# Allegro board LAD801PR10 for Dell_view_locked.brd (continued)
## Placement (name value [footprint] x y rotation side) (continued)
JPWR1  JXT_FP226H-006S1BM  [JXT_FP226H-006S1BM_6P]  159.15 107.31 90 top
JRTC1  ACES_50271-0020N-001  [ACES_50271-0020N-001_2P]  29.83 5.9 180 bottom
JSPK1  JXT_WB247H-004S10M  [JXT_WB247H-004S10M_4P]  11.81 5.67 180 bottom
JSSD1  ACES_50406-03071-001  [ACES_50406-03071-001_30P]  198.85 14.1 180 top
JTP1  JXT_FP202DH-008M10M  [JXT_FP202DH-008M10M_8P]  104.9 9.71 180 bottom
JUSB1  ACON_TARA4-9K1311  [ACON_TARA4-9K1311_9P]  14.68 63.2 90 bottom
JUSB2  ACON_TARA4-9K1311  [ACON_TARA4-9K1311_9P]  14.68 41.5 90 bottom
JWLAN1  LCN_DAN05-67406-0100  [LCN_DAN05-67406-0100_67P]  43.05 100.18 0 bottom
L1  BLM15BD601SN1D_2P  [MURAT_BLM15BD601SN1D_2P]  134.04 43.43 90 top
L2  BLM15BD601SN1D_2P  [MURAT_BLM15BD601SN1D_2P]  91.27 40.98 0 top
L3  MCM1012B900F06BP_4P  [INPAQ_MCM1012B900F06BP_4P]  221.75 35.14 180 bottom
L4  MCM1012B900F06BP_4P  [INPAQ_MCM1012B900F06BP_4P-NPM]  220.88 26.81 270 bottom
L5  BLM15PX221SN1D_2P  [MURAT_BLM15PX221SN1D_2P]  31.13 28.23 270 top
LI1  HCM1012GH900BP_4P  [INPAQ_HCM1012GH900BP_4P-NPM]  16.21 87.01 0 top
LI2  HCM1012GH900BP_4P  [INPAQ_HCM1012GH900BP_4P-NPM]  16.21 89.55 0 top
LI3  HCM1012GH900BP_4P  [INPAQ_HCM1012GH900BP_4P-NPM]  16.21 81.93 0 top
LI4  HCM1012GH900BP_4P  [INPAQ_HCM1012GH900BP_4P-NPM]  16.21 84.47 0 top
LU1  MCM1012B900F06BP_4P  [INPAQ_MCM1012B900F06BP_4P]  25.17 57.68 0 top
LU2  HCM1012GH900BP_4P  [INPAQ_HCM1012GH900BP_4P-NPM]  22.44 62.31 0 top
LU3  HCM1012GH900BP_4P  [INPAQ_HCM1012GH900BP_4P-NPM]  22.44 60.54 0 top
LU4  MCM1012B900F06BP_4P  [INPAQ_MCM1012B900F06BP_4P]  25.68 35.9 0 top
LU5  HCM1012GH900BP_4P  [INPAQ_HCM1012GH900BP_4P-NPM]  22.63 41.23 0 top
LU6  HCM1012GH900BP_4P  [INPAQ_HCM1012GH900BP_4P-NPM]  22.76 38.88 0 top
LU7  MCM1012B900F06BP_4P  [INPAQ_MCM1012B900F06BP_4P]  174.8 20.25 180 bottom
LU8  MCM1012B900F06BP_4P  [INPAQ_MCM1012B900F06BP_4P]  180.82 20.25 180 bottom
LV2  BLM15BD121SN1D_0402  [R_0402]  99.23 115.37 270 top
LV3  BLM15BD121SN1D_0402  [R_0402]  99.41 118.96 270 top
LV4  BLM15BD121SN1D_0402  [R_0402]  97.89 115.1 90 bottom
LV6  BLM15BD221SN1D_2P  [MURAT_BLM15BB221SN1D_2P]  115.58 104.6 90 top
LV7  BLM15BD121SN1D_0402  [R_0402]  120.34 100.07 0 top
LV8  BLM15BD121SN1D_0402  [R_0402]  123.1 100.22 180 top
LW1  MCM1012B900F06BP_4P  [INPAQ_MCM1012B900F06BP_4P-NPM]  42.12 97.46 270 bottom
LX1  MCF12102G900-T_4P  [TAIYO_MCF12102G900-T_4P]  218.36 44.01 270 bottom
LX2  MCF12102G900-T_4P  [TAIYO_MCF12102G900-T_4P]  216.56 43.97 270 bottom
NOREF  -  []  82.28 86.9 0 top
NOREF#2  -  []  77.34 41.48 0 top
NOREF#3  -  []  88.93 117.7 0 top
NOREF#4  -  []  206.6 47.9 0 top
NOREF#5  -  []  52.3 133.7 0 top
NOREF#6  -  []  38.63 56.48 270 top
NOREF#7  -  []  49.63 8.4 0 top
NOREF#8  -  []  -44.7 133.66 0 top
NOREF#9  -  []  166 99.8 0 top
NOREF#10  -  []  27.76 -37.89 0 top
NOREF#11  -  []  100 80.45 0 top
NOREF#12  -  []  18.4 4.3 0 top
NOREF#13  -  []  141.9 6.3 0 top
NOREF#14  -  []  113.5 134.5 0 top
NOREF#15  -  []  5 3.6 0 top
NOREF#16  -  []  82.24 66.05 0 top
NOREF#17  -  []  124.3 17.25 0 top
NOREF#18  -  []  34.53 73.04 270 top
NOREF#19  -  []  121.2 136 0 top
NOREF#20  -  []  141.9 61.2 0 top
NOREF#21  -  []  124.3 80.45 0 top
NOREF#22  -  []  -0.3 173.69 0 top
NOREF#23  -  []  8.7 122.3 0 top
NOREF#24  -  []  136.5 90.5 0 top
NOREF#25  -  []  100 17.25 0 top
NOREF#26  -  []  73.4 94.39 180 bottom
NOREF#27  -  []  81.35 29.7 90 bottom
NOREF#28  -  []  107.37 95.09 180 bottom
PBATT1  -  [ACES_50458-01001-P01_10P-T]  225.91 17.6 180 bottom
PC1  1000P_0402_50V7K  [C_0402]  157.51 123.91 180 top
PC2  0.1U_0402_25V7K  [C_0402]  157.51 122.96 180 top
PC3  1000P_0402_50V7K  [C_0402]  156.75 118.77 180 top
PC4  0.1U_0402_25V7K  [C_0402]  156.75 119.66 180 top
PC7  0.01U_0402_25V7K  [C_0402]  200.55 19.53 270 bottom
PC8  1000P_0402_50V7K  [C_0402]  203.47 15.28 270 bottom
PC14  .1U_0402_16V7K  [C_0402]  179.11 27.47 0 top
PC16  .1U_0402_16V7K  [C_0402]  178.26 21.98 90 top
PC100  1000P_0402_25V8J  [C_0402]  179.34 44.17 270 top
PC102  0.1U_0402_10V7K  [C_0402]  172.27 46.45 270 bottom
PC103  2200P_0402_50V7K  [C_0402]  178.45 44.17 270 bottom
PC104  10U_0805_25V6K  [C_0805]  176.72 45.89 0 top
PC105  10U_0805_25V6K  [C_0805]  176.72 45.89 0 bottom
PC106  22U_0805_6.3V6M  [C_0805]  161.53 40.21 270 bottom
PC107  22U_0805_6.3V6M  [C_0805]  163.3 39.45 270 bottom
PC108  22U_0805_6.3V6M  [C_0805]  160.45 42.82 90 bottom
PC109  22U_0805_6.3V6M  [C_0805]  159.75 40.21 270 bottom
PC110  22U_0805_6.3V6M  [C_0805]  162.24 42.82 90 bottom
PC111  4.7U_0603_6.3V6M  [C_0603]  177.16 41.76 90 top
PC112  680P_0603_50V7K  [C_0603]  166.58 43.08 270 top
PC113  1000P_0402_25V8J  [C_0402]  175.28 39.6 270 bottom
PC114  0.1U_0402_10V7K  [C_0402]  174.9 36.49 270 bottom
PC115  1000P_0402_25V8J  [C_0402]  182.07 34.38 270 top
PC116  2200P_0402_50V7K  [C_0402]  181.18 34.39 270 bottom
PC117  10U_0805_25V6K  [C_0805]  179.75 35.92 0 bottom
PC118  10U_0805_25V6K  [C_0805]  179.75 35.9 0 top
PC119  4.7U_0603_6.3V6M  [C_0603]  176.68 31.46 0 top
PC120  22U_0805_6.3V6M  [C_0805]  174.94 23.2 0 bottom
PC121  22U_0805_6.3V6M  [C_0805]  174.94 24.92 0 bottom
PC122  22U_0805_6.3V6M  [C_0805]  174.94 26.63 0 bottom
PC123  22U_0805_6.3V6M  [C_0805]  170.67 23.71 180 bottom
PC124  22U_0805_6.3V6M  [C_0805]  170.67 25.42 180 bottom
PC125  680P_0603_50V7K  [C_0603]  173.18 30.95 180 top
PC126  4.7U_0603_6.3V6M  [C_0603]  176.23 29.36 270 bottom
PC127  1000P_0402_25V8J  [C_0402]  179.09 29.37 270 bottom
PC128  4.7U_0402_6.3V6M  [C_0402]  181.74 29.36 0 bottom
PC130  0.1U_0402_25V6  [C_0402]  179.34 44.17 270 bottom
PC131  1000P_0402_25V8J  [C_0402]  178.45 44.17 270 top
PC132  0.1U_0402_25V6  [C_0402]  181.19 34.38 270 top
PC133  1000P_0402_25V8J  [C_0402]  182.07 34.39 270 bottom
PC200  0.1U_0402_10V7K  [C_0402]  85.55 108.75 270 bottom
PC201  2200P_0402_50V7K  [C_0402]  81.86 109.14 0 bottom
PC202  0.1U_0402_10V7K  [C_0402]  88.41 101.64 270 bottom
PC203  0.1U_0402_10V7K  [C_0402]  89.3 101.64 270 bottom
PC204  1U_0603_10V6K  [C_0603]  82.57 104.86 0 bottom
PC205  10U_0805_6.3V6K  [C_0805]  93.17 105.47 90 bottom
PC206  10U_0805_25V6K  [C_0805]  81.53 107.85 0 top
PC207  680P_0402_50V7K  [C_0402]  76.74 103.78 180 top
PC208  0.1U_0402_25V6  [C_0402]  81.86 109.14 0 top
PC209  1U_0603_10V6K  [C_0603]  84.47 101.24 270 bottom
PC210  0.033U_0402_16V7K  [C_0402]  91.06 104.42 0 bottom
PC211  10U_0805_6.3V6K  [C_0805]  91.46 105.47 90 bottom
PC212  10U_0805_25V6K  [C_0805]  81.53 107.85 0 bottom
PC213  .1U_0402_16V7K  [C_0402]  91.06 103.53 0 bottom
PC214  220P_0402_25V8J  [C_0402]  91.07 101.71 90 bottom
PC215  22U_0603_6.3V6M  [C_0603]  67.3 105.68 90 top
PC216  22U_0603_6.3V6M  [C_0603]  66.03 105.68 90 top
PC217  22U_0603_6.3V6M  [C_0603]  66.02 105.68 90 bottom
PC218  22U_0603_6.3V6M  [C_0603]  64.76 105.68 90 bottom
PC219  22U_0603_6.3V6M  [C_0603]  64.76 105.68 90 top
PC220  22U_0603_6.3V6M  [C_0603]  67.29 105.68 90 bottom
PC230  1000P_0402_25V8J  [C_0402]  81.86 110.03 0 top
PC231  1000P_0402_25V8J  [C_0402]  81.86 110.03 0 bottom
PC301  2200P_0402_50V7K  [C_0402]  155.21 43.34 270 bottom
PC302  0.1U_0402_25V6  [C_0402]  157.88 43.34 270 bottom
PC303  10U_0805_25V6K  [C_0805]  153.88 44.31 270 bottom
PC304  0.1U_0402_25V6  [C_0402]  154.39 40.4 90 bottom
PC305  1U_0402_6.3V6K  [C_0402]  147.28 39.66 270 bottom
PC306  2.2U_0402_6.3V6M  [C_0402]  146.39 39.66 270 bottom
PC307  0.1U_0402_10V7K  [C_0402]  147.72 46.58 270 bottom
PC308  680P_0603_50V7K  [C_0603]  142.39 46.7 180 bottom
PC309  330P_0402_50V7K  [C_0402]  149.93 38.63 0 bottom
PC310  22U_0603_6.3V6M  [C_0603]  140.48 39.71 270 bottom
PC311  22U_0603_6.3V6M  [C_0603]  139.21 39.71 270 bottom
PC312  22U_0603_6.3V6M  [C_0603]  139.85 45.93 90 bottom
PC313  22U_0603_6.3V6M  [C_0603]  138.58 45.93 90 bottom
PC320  2200P_0402_50V7K  [C_0402]  156.99 43.34 270 bottom
PC321  0.1U_0402_25V6  [C_0402]  156.1 43.34 270 bottom
PC501  22U_0603_6.3V6M  [C_0603]  159.34 37.34 0 bottom
PC502  0.1U_0402_10V7K  [C_0402]  160.79 32.79 0 bottom
PC503  22P_0402_50V8J  [C_0402]  159.92 32.79 180 bottom
PC504  680P_0402_50V7K  [C_0402]  162.21 35.01 180 top
PC505  22U_0603_6.3V6M  [C_0603]  166.02 26.62 0 bottom
PC506  22U_0603_6.3V6M  [C_0603]  166.02 27.87 0 bottom
PC507  22U_0603_6.3V6M  [C_0603]  166.02 27.87 0 top
PC601  680P_0402_50V7K  [C_0402]  157.96 55.84 180 top
PC602  0.1U_0402_25V6  [C_0402]  167.2 48.85 0 bottom
PC603  1U_0603_10V6K  [C_0603]  163.66 50.88 90 bottom
PC604  0.22U_0603_25V7K  [C_0603]  162.64 46.82 180 top
PC605  47P_0402_50V8J~D  [C_0402]  169.56 48.8 270 top
PC606  33U_25V_M  [C_25CL33LD]  161.75 66.91 270 bottom
PC608  10U_0805_25V6K  [C_0805]  149.22 58.7 0 bottom
PC611  0.22U_0402_16V7K  [C_0402]  153.19 54.12 0 bottom
PC612  10U_0805_25V6K  [C_0805]  149.22 60.48 0 bottom
PC613  330P_0402_50V8J  [C_0402]  166.69 51.38 0 bottom
PC614  2200P_0402_50V7K  [C_0402]  165.42 53.93 0 bottom
PC616  33P_0402_50V8J  [C_0402]  166.25 52.27 0 bottom
PC617  220P_0402_50V7K  [C_0402]  169.8 54.13 0 top
PC618  330P_0402_50V7K  [C_0402]  170.72 53.24 180 bottom
PC619  0.01U_0402_50V7K  [C_0402]  170.72 52.35 180 bottom
PC620  0.082U_0402_16V7K  [C_0402]  168.93 53.25 270 bottom
PC621  680P_0402_50V7K  [C_0402]  169.8 51.44 0 top
PC622  680P_0603_50V7K  [C_0603]  146.77 55.46 0 top
PC624  0.068U_0402_16V7K  [C_0402]  168.93 54.43 90 bottom
PC625  330P_0402_50V7K  [C_0402]  165.24 55.27 90 bottom
PC626  0.033U_0402_16V7K  [C_0402]  169.82 54.43 90 bottom
PC627  2200P_0402_50V7K  [C_0402]  169.83 55.33 180 top
PC628  10P_0402_50V8J  [C_0402]  161.42 52.91 0 bottom
PC629  2200P_0402_50V7K  [C_0402]  161.68 55.78 0 bottom
PC630  2200P_0402_50V7K  [C_0402]  159.72 56.72 90 top
PC631  1200P_0402_50V7K  [C_0402]  162.32 51.13 90 bottom
PC632  2200P_0402_25V7K  [C_0402]  159.67 50.13 180 top
PC633  6800P_0402_25V7K  [C_0402]  159.66 52.81 270 top
PC636  33P_0402_50V8J  [C_0402]  164.35 55.27 90 bottom
PC637  0.033U_0402_16V7K  [C_0402]  157.88 52.81 270 top
PC639  2200P_0402_25V7K  [C_0402]  163.34 58.3 90 top
PC640  2200P_0402_25V7K  [C_0402]  157.94 54.96 270 top
PC641  .1U_0402_16V7K  [C_0402]  171.09 56.21 90 bottom
PC642  0.047U_0402_25V7K  [C_0402]  159.23 56.73 180 bottom
PC643  330P_0402_50V7K  [C_0402]  161.42 53.81 0 bottom
PC644  .1U_0402_16V7K  [C_0402]  156.99 50.11 90 top
PC645  .1U_0402_16V7K  [C_0402]  157.44 57.63 270 bottom
PC646  0.047U_0402_25V7K  [C_0402]  159.23 57.62 180 bottom
PC647  680P_0402_50V7K  [C_0402]  167.28 59.26 90 top
PC649  0.01U_0402_50V7K  [C_0402]  159.73 54.95 180 bottom
PC650  0.082U_0402_16V7K  [C_0402]  158.82 54.06 0 bottom
PC651  330P_0402_50V7K  [C_0402]  162.45 59.22 270 top
PC652  330P_0402_50V7K  [C_0402]  157.94 54.05 90 bottom
PC653  0.082U_0402_16V7K  [C_0402]  162.46 57.43 180 top
PC654  0.01U_0402_50V7K  [C_0402]  161.05 59.22 270 top
PC655  0.22U_0402_16V7K  [C_0402]  163.16 69.81 180 bottom
PC656  10U_0805_25V6K  [C_0805]  157.63 68.1 180 top
PC657  10U_0805_25V6K  [C_0805]  157.63 66.32 180 bottom
PC658  10U_0805_25V6K  [C_0805]  157.64 68.05 180 bottom
PC659  0.1U_0402_25V6K~D  [C_0402]  157.75 64.92 180 top
PC660  2200P_0402_50V7K  [C_0402]  157.75 63.97 180 bottom
PC661  1U_0402_10V6K  [C_0402]  162.31 72.54 0 bottom
PC662  680P_0603_50V7K  [C_0603]  153.12 69.43 0 top
PC666  0.1U_0402_25V6K~D  [C_0402]  158.95 74.77 180 top
PC667  2200P_0402_50V7K  [C_0402]  158.77 74.62 180 bottom
PC671  0.22U_0402_16V7K  [C_0402]  163.18 79.59 180 bottom
PC672  10U_0805_25V6K  [C_0805]  159.06 75.94 180 bottom
PC673  10U_0805_25V6K  [C_0805]  159.06 77.67 180 bottom
PC677  1U_0402_10V6K  [C_0402]  162.25 82.13 0 bottom
PC678  680P_0603_50V7K  [C_0603]  153.37 78.19 270 top
PC679  1000P_0402_50V7K  [C_0402]  158.97 78.32 180 top
PC680  1000P_0402_50V7K  [C_0402]  157.7 65.87 180 top
PC685  1U_0402_10V6K  [C_0402]  151.15 51.7 90 top
PC686  10P_0402_25V8J  [C_0402]  157.75 64.92 180 bottom
PC688  10P_0402_25V8J  [C_0402]  158.97 76.54 180 top
PC690  33U_25V_M  [C_25CL33LD]  169.21 67.02 270 bottom
PC691  1000P_0402_25V8J  [C_0402]  157.75 63.97 180 top
PC692  1000P_0402_25V8J  [C_0402]  158.97 77.43 180 top
PC693  1000P_0402_25V8J  [C_0402]  158.97 75.66 180 top
PC694  1000P_0402_25V8J  [C_0402]  157.69 66.76 180 top
PC695  10P_0402_25V8J  [C_0402]  168.3 47.77 180 bottom
PC705  2200P_0402_25V7K  [C_0402]  198.96 30.11 90 bottom
PC708  0.1U_0402_25V6  [C_0402]  194.38 40.16 0 bottom
PC711  0.01UF_0402_25V7K  [C_0402]  189.81 32.23 0 top
PC721  0.22U_0402_16V7K  [C_0402]  199.74 35.33 180 bottom
PC742  5600P_0402_25V7K  [C_0402]  156.62 108.23 180 bottom
PC744  0.1U_0402_25V6  [C_0402]  158.57 109.24 0 bottom
PC747  0.1U_0402_25V6  [C_0402]  193.58 32.15 180 bottom
PC748  0.1U_0402_25V7K  [C_0402]  188.94 37.93 180 bottom
PC749  2200P_0402_25V7K  [C_0402]  188.03 39.33 0 bottom
PC750  0.22U_0603_25V7K  [C_0603]  194.71 30.69 90 bottom
PC751  560P_0402_50V7K  [C_0402]  190.39 42.01 270 bottom
PC752  0.015U_0402_25V7K  [C_0402]  190.38 42.89 0 bottom
PC753  10P_0402_50V8J  [C_0402]  192.6 41.93 0 bottom
PC757  1U_0603_25V6  [C_0603]  199.42 38.93 180 bottom
PC760  10U_0805_25V6K  [C_0805]  200.25 30.02 90 bottom
PC761  10U_0805_25V6K  [C_0805]  215.58 23.84 0 bottom
PC762  10U_0805_25V6K  [C_0805]  200.25 30.02 90 top
PC763  10U_0805_25V6K  [C_0805]  201.96 30.02 90 top
PC764  10U_0805_25V6K  [C_0805]  201.96 30.02 90 bottom
PC765  0.1U_0402_25V7K  [C_0402]  198.08 30.11 90 bottom
PC766  10U_0805_25V6K  [C_0805]  215.59 22.12 0 bottom
PC767  680P_0603_50V7K  [C_0603]  210.46 33.81 270 top
PC768  1U_0402_16V6K  [C_0402]  200.18 37.68 180 bottom
PC769  1U_0402_16V6K  [C_0402]  200.18 36.79 180 bottom
PC775  10U_0805_25V6K  [C_0805]  214.14 21.77 270 bottom
PC776  10U_0805_25V6K  [C_0805]  215.58 22.12 0 top
PC777  0.1U_0402_25V7K  [C_0402]  215.72 25.17 0 bottom
PC778  10U_0805_25V6K  [C_0805]  215.58 23.83 0 top
PC779  0.1U_0402_25V7K  [C_0402]  210.01 25.69 270 top
PC780  1000P_0402_25V8J  [C_0402]  198.96 30.11 90 top
PC781  1000P_0402_25V8J  [C_0402]  198.08 30.11 90 top
PC790  0.01U_0402_16V7K  [C_0402]  187.9 37.93 0 top
PC801  1U_0402_6.3V6K  [C_0402]  52.11 3.15 0 bottom
PC802  10U_0805_10V6K  [C_0805]  54.42 5.29 270 bottom
PC803  0.01U_0402_25V7K  [C_0402]  44.32 6.69 90 bottom
PC804  10U_0805_10V6K  [C_0805]  44.9 5.48 270 bottom
PC805  0.1U_0402_10V6K  [C_0402]  53.99 8.57 0 bottom
PC836  330U_2V_M  [C_5X4P5]  86.91 124.92 180 bottom
PC837  330U_2V_M  [C_5X4P5]  86.97 131.08 180 bottom
PC838  330U_2V_M  [C_5X4P5]  81.02 120.86 0 bottom
PC839  330U_2V_M  [C_5X4P5]  89.01 110.57 180 bottom
PC1001  22U_0603_6.3V6M  [C_0603]  116.57 46.72 90 top
PC1002  22U_0603_6.3V6M  [C_0603]  134.26 60.65 180 bottom
PC1003  22U_0603_6.3V6M  [C_0603]  134.26 64.72 180 bottom
PC1004  22U_0603_6.3V6M  [C_0603]  133.18 67.64 180 bottom
PC1005  22U_0603_6.3V6M  [C_0603]  115.36 46.72 90 top
PC1006  22U_0603_6.3V6M  [C_0603]  133.18 69.04 180 bottom
PC1007  22U_0603_6.3V6M  [C_0603]  111.74 46.7 90 top
PC1008  22U_0603_6.3V6M  [C_0603]  114.15 46.72 90 top
PC1009  22U_0603_6.3V6M  [C_0603]  112.95 46.7 90 top
PC1010  22U_0603_6.3V6M  [C_0603]  116.57 50.5 270 top
PC1011  22U_0603_6.3V6M  [C_0603]  115.36 50.49 270 top
PC1012  22U_0603_6.3V6M  [C_0603]  133.18 70.43 180 bottom
PC1013  22U_0603_6.3V6M  [C_0603]  133.18 71.83 180 bottom
PC1014  22U_0603_6.3V6M  [C_0603]  132.8 80.09 180 bottom
PC1015  22U_0603_6.3V6M  [C_0603]  132.8 78.69 180 bottom
PC1016  22U_0603_6.3V6M  [C_0603]  112.67 76.92 0 bottom
PC1017  22U_0603_6.3V6M  [C_0603]  116.48 80.73 180 bottom
PC1018  22U_0603_6.3V6M  [C_0603]  112.67 75.65 0 bottom
PC1019  22U_0603_6.3V6M  [C_0603]  112.67 79.46 0 bottom
PC1020  22U_0603_6.3V6M  [C_0603]  112.67 80.73 0 bottom
PC1021  22U_0603_6.3V6M  [C_0603]  116.48 79.46 180 bottom
PC1022  22U_0603_6.3V6M  [C_0603]  112.67 78.19 0 bottom
PC1023  22U_0603_6.3V6M  [C_0603]  111.01 58.88 270 top
PC1024  22U_0603_6.3V6M  [C_0603]  114.62 58.88 270 top
PC1025  22U_0603_6.3V6M  [C_0603]  132.8 82.88 180 bottom
PC1026  22U_0603_6.3V6M  [C_0603]  109.8 58.88 270 top
PC1027  22U_0603_6.3V6M  [C_0603]  132.8 77.36 180 bottom
PC1028  22U_0603_6.3V6M  [C_0603]  114.64 61.3 270 top
PC1029  22U_0603_6.3V6M  [C_0603]  115.84 61.3 270 top
PC1030  1U_0201_6.3V6M  [C_0201]  108.1 48.63 270 top
PC1031  1U_0201_6.3V6M  [C_0201]  110.22 53.87 270 top
PC1032  1U_0201_6.3V6M  [C_0201]  110.81 48.18 90 top
PC1033  1U_0201_6.3V6M  [C_0201]  109.05 53.87 270 top
PC1034  1U_0201_6.3V6M  [C_0201]  109.67 50.41 270 top
PC1035  1U_0201_6.3V6M  [C_0201]  110.8 53.87 270 top
PC1036  1U_0201_6.3V6M  [C_0201]  109.68 48.18 90 top
PC1037  1U_0201_6.3V6M  [C_0201]  110.25 48.18 90 top
PC1038  1U_0201_6.3V6M  [C_0201]  108.1 49.38 90 top
PC1039  1U_0201_6.3V6M  [C_0201]  110.23 50.41 270 top
PC1040  1U_0201_6.3V6M  [C_0201]  111.15 61.46 270 top
PC1041  1U_0201_6.3V6M  [C_0201]  110 61.46 270 top
PC1042  1U_0201_6.3V6M  [C_0201]  108.31 58.18 0 top
PC1043  1U_0201_6.3V6M  [C_0201]  110.74 56.15 270 top
PC1044  1U_0201_6.3V6M  [C_0201]  111.32 56.15 270 top
PC1045  1U_0201_6.3V6M  [C_0201]  109.58 56.15 270 top
PC1046  1U_0201_6.3V6M  [C_0201]  110.03 60.28 0 top
PC1047  1U_0201_6.3V6M  [C_0201]  110.17 56.15 270 top
PC1048  1U_0201_6.3V6M  [C_0201]  117.34 54.37 180 top
PC1049  1U_0201_6.3V6M  [C_0201]  109.01 56.14 270 top
PC1050  1U_0201_6.3V6M  [C_0201]  110.8 50.4 270 top
PC1051  1U_0201_6.3V6M  [C_0201]  111.51 54.34 0 top
PC1052  1U_0201_6.3V6M  [C_0201]  111.51 53.74 0 top
PC1053  1U_0201_6.3V6M  [C_0201]  110.78 51.62 90 top
PC1054  1U_0201_6.3V6M  [C_0201]  110.22 51.62 90 top
PC1055  1U_0201_6.3V6M  [C_0201]  117.34 53.8 180 top
PC1056  1U_0201_6.3V6M  [C_0201]  110.03 59.71 0 top
PC1057  22U_0603_6.3V6M  [C_0603]  117.24 43.2 90 top
PC1058  22U_0603_6.3V6M  [C_0603]  137.44 51.7 180 top
PC1059  22U_0603_6.3V6M  [C_0603]  137.44 53.1 180 top
PC1060  22U_0603_6.3V6M  [C_0603]  137.44 54.75 180 top
PC1061  22U_0603_6.3V6M  [C_0603]  116.54 51.54 90 top
PC1062  220U 2V Y D2  [C_D2]  137.18 69.02 90 bottom
PC1063  330U_2V_M  [C_5X4P5]  136.33 79.86 270 bottom
PC1064  22U_0603_6.3V6M  [C_0603]  115.34 51.53 90 top
PC1065  22U_0603_6.3V6M  [C_0603]  114.13 51.53 90 top
PC1066  22U_0603_6.3V6M  [C_0603]  112.92 51.53 90 top
PC1067  22U_0603_6.3V6M  [C_0603]  111.72 51.53 90 top
PC1068  22U_0603_6.3V6M  [C_0603]  133.18 66.24 180 bottom
PC1069  22U_0603_6.3V6M  [C_0603]  136.61 64.72 180 bottom
PC1070  22U_0603_6.3V6M  [C_0603]  135.53 66.5 180 top
PC1071  22U_0603_6.3V6M  [C_0603]  135.53 69.29 180 top
PC1072  22U_0603_6.3V6M  [C_0603]  134.26 62.05 180 bottom
PC1073  22U_0603_6.3V6M  [C_0603]  135.53 67.89 180 top
PC1074  22U_0603_6.3V6M  [C_0603]  138.01 67.13 180 top
PC1075  22U_0603_6.3V6M  [C_0603]  138.01 65.73 180 top
PC1076  22U_0603_6.3V6M  [C_0603]  134.26 64.72 180 top
PC1077  22U_0603_6.3V6M  [C_0603]  134.26 63.32 180 top
PC1078  22U_0603_6.3V6M  [C_0603]  133.18 71.83 180 top
PC1079  22U_0603_6.3V6M  [C_0603]  133.18 70.43 180 top
PC1080  22U_0603_6.3V6M  [C_0603]  133.18 69.04 180 top
PC1081  22U_0603_6.3V6M  [C_0603]  133.18 67.64 180 top
PC1082  22U_0603_6.3V6M  [C_0603]  133.18 66.24 180 top
PC1083  1U_0201_6.3V6M  [C_0201]  109.62 51.61 90 top
PC1084  1U_0201_6.3V6M  [C_0201]  109.05 51.61 90 top
PC1085  1U_0201_6.3V6M  [C_0201]  118.96 49.5 270 top
PC1086  1U_0201_6.3V6M  [C_0201]  110.24 47.11 270 top
PC1087  1U_0201_6.3V6M  [C_0201]  110.81 47.11 270 top
PC1088  1U_0201_6.3V6M  [C_0201]  109.63 53.87 270 top
PC1089  1U_0201_6.3V6M  [C_0201]  117.27 45.92 180 top
PC1090  1U_0201_6.3V6M  [C_0201]  117.27 45.36 180 top
PC1091  1U_0201_6.3V6M  [C_0201]  112.17 45.36 0 top
PC1092  1U_0201_6.3V6M  [C_0201]  114.42 45.93 180 top
PC1093  1U_0201_6.3V6M  [C_0201]  115.03 45.36 0 top
PC1094  1U_0201_6.3V6M  [C_0201]  115.03 45.93 0 top
PC1095  1U_0201_6.3V6M  [C_0201]  114.42 45.36 180 top
PC1096  1U_0201_6.3V6M  [C_0201]  112.17 45.93 0 top
PC1097  1U_0201_6.3V6M  [C_0201]  111.55 45.93 180 top
PC1098  1U_0201_6.3V6M  [C_0201]  111.56 45.36 180 top
PC1099  1U_0201_6.3V6M  [C_0201]  109.33 45.93 0 top
PC1103  10U_0805_25V6K  [C_0805]  66.17 127.67 270 bottom
PC1104  10U_0805_25V6K  [C_0805]  66.17 114.32 90 top
PC1105  10U_0805_25V6K  [C_0805]  66.17 114.32 90 bottom
PC1106  2200P_0402_50V7K  [C_0402]  64 126.95 270 bottom
PC1107  0.1U_0402_25V6K  [C_0402]  63.96 114.54 90 bottom
PC1108  0.22U_0402_16V7K  [C_0402]  59.72 124.48 180 top
PC1109  680P_0603_50V7K  [C_0603]  67.79 129.06 270 top
PC1110  1U_0603_10V6K  [C_0603]  58.44 128.93 270 top
PC1111  1U_0603_10V6K  [C_0603]  56.03 127.53 90 top
PC1112  10U_0805_25V6K  [C_0805]  66.17 127.67 270 top
PC1113  10U_0805_25V6K  [C_0805]  62.69 127.11 270 top
PC1114  10U_0805_25V6K  [C_0805]  62.31 114.3 90 top
PC1115  2200P_0402_50V7K  [C_0402]  64.85 114.54 90 bottom
PC1116  0.1U_0402_25V6  [C_0402]  64.89 126.95 270 bottom
PC1117  1000P_0402_50V7K  [C_0402]  48.2 120.48 0 top
PC1118  0.22U_0402_16V7K  [C_0402]  59.34 121.69 180 top
PC1119  0.22U_0402_10V6K  [C_0402]  50.18 117.8 90 top
PC1120  0.22U_0402_10V6K  [C_0402]  51.07 117.8 90 top
PC1121  680P_0603_50V7K  [C_0603]  69.7 114.64 180 top
PC1122  1000P_0402_50V7K  [C_0402]  53.92 116.42 0 top
PC1123  180P_0402_50V8J  [C_0402]  57.6 118.71 0 top
PC1124  330P_0402_50V7K  [C_0402]  53.92 118.71 0 top
PC1125  1U_0201_6.3V6M  [C_0201]  109.33 45.36 0 top
PC1126  1U_0201_6.3V6M  [C_0201]  109.67 47.11 270 top
PC1127  220U 2V Y D2  [C_D2]  142.7 69.02 90 bottom
PC1128  330U_2V_M  [C_5X4P5]  142.45 79.86 270 bottom
PC1129  22U_0603_6.3V6M  [C_0603]  117.05 58.88 270 top
PC1130  22U_0603_6.3V6M  [C_0603]  116.48 76.92 180 bottom
PC1131  22U_0603_6.3V6M  [C_0603]  112.22 61.3 270 top
PC1132  22U_0603_6.3V6M  [C_0603]  116.48 75.65 180 bottom
PC1133  22U_0603_6.3V6M  [C_0603]  115.84 58.88 270 top
PC1134  22U_0603_6.3V6M  [C_0603]  113.43 58.88 270 top
PC1135  22U_0603_6.3V6M  [C_0603]  112.21 58.88 270 top
PC1136  22U_0603_6.3V6M  [C_0603]  116.48 78.19 180 bottom
PC1137  22U_0603_6.3V6M  [C_0603]  117.05 61.3 270 top
PC1138  22U_0603_6.3V6M  [C_0603]  113.43 61.3 270 top
PC1139  22U_0603_6.3V6M  [C_0603]  137.44 54.75 180 bottom
PC1140  22U_0603_6.3V6M  [C_0603]  137.43 51.71 180 bottom
PC1141  22U_0603_6.3V6M  [C_0603]  137.44 53.1 180 bottom
PC1142  22U_0603_6.3V6M  [C_0603]  114.83 43.2 90 top
PC1143  22U_0603_6.3V6M  [C_0603]  113.62 43.2 90 top
PC1144  22U_0603_6.3V6M  [C_0603]  112.42 43.2 90 top
PC1145  22U_0603_6.3V6M  [C_0603]  111.21 43.2 90 top
PC1146  22U_0603_6.3V6M  [C_0603]  116.03 43.2 90 top
PC1147  1U_0201_6.3V6M  [C_0201]  109.75 43.87 90 top
PC1148  1U_0201_6.3V6M  [C_0201]  109.19 43.87 90 top
PC1149  1U_0201_6.3V6M  [C_0201]  110.79 42.44 0 top
PC1150  1U_0201_6.3V6M  [C_0201]  110 42.73 270 top
PC1151  1U_0201_6.3V6M  [C_0201]  109.43 43.24 270 top
PC1152  1U_0201_6.3V6M  [C_0201]  113.82 42.36 180 top
PC1153  1U_0201_6.3V6M  [C_0201]  110.31 43.87 90 top
PC1164  1U_0201_6.3V6M  [C_0201]  107.5 50.51 180 top
PC1170  22U_0603_6.3V6M  [C_0603]  114.15 50.49 270 top
PC1171  22U_0603_6.3V6M  [C_0603]  111.74 50.49 270 top
PC1172  22U_0603_6.3V6M  [C_0603]  112.95 50.49 270 top
PC1173  22U_0603_6.3V6M  [C_0603]  136.61 63.32 180 bottom
PC1174  22U_0603_6.3V6M  [C_0603]  134.26 63.32 180 bottom
PC1175  22U_0603_6.3V6M  [C_0603]  113.43 56.53 270 top
PC1176  22U_0603_6.3V6M  [C_0603]  117.05 56.53 270 top
PC1177  22U_0603_6.3V6M  [C_0603]  115.84 56.53 270 top
PC1178  22U_0603_6.3V6M  [C_0603]  113.43 74.38 0 bottom
PC1179  22U_0603_6.3V6M  [C_0603]  132.8 84.28 180 bottom
PC1180  22U_0603_6.3V6M  [C_0603]  112.64 75.65 0 top
PC1181  22U_0603_6.3V6M  [C_0603]  114.64 56.53 270 top
PC1182  22U_0603_6.3V6M  [C_0603]  116.48 75.65 180 top
PC1183  22U_0603_6.3V6M  [C_0603]  112.22 56.53 270 top
PC1184  22U_0603_6.3V6M  [C_0603]  132.8 81.48 180 bottom
PC1190  2200P_0402_50V7K  [C_0402]  64.89 126.95 270 top
PC1191  0.1U_0402_25V6K  [C_0402]  64 126.95 270 top
PC1192  2200P_0402_50V7K  [C_0402]  64.85 114.54 90 top
PC1193  0.1U_0402_25V6  [C_0402]  63.96 114.54 90 top
PC1226  0.1U_0402_25V6K  [C_0402]  49.12 124.93 180 top
PC1227  820P_0402_50V7K  [C_0402]  53.04 117.8 90 top
PC1228  390P_0402_50V7K  [C_0402]  58.5 116.91 90 top
PC1229  0.01U_0402_50V7K  [C_0402]  56.61 118.71 180 top
PC1230  0.15U_0603_16V7K  [C_0603]  50.25 116.74 0 top
PC1231  0.1U_0603_50V7K  [C_0603]  53.99 114.2 0 top
PC1232  0.033U_0402_16V7K  [C_0402]  50.11 115.66 0 top
PC1233  330P_0402_50V  [C_0402]  57.5 115.02 180 top
PC1401  2200P_0402_50V7K  [C_0402]  159.07 96.42 0 bottom
PC1402  0.1U_0402_25V6  [C_0402]  159.07 97.31 0 bottom
PC1403  10U_0805_25V6K  [C_0805]  158.36 93.3 0 bottom
PC1404  0.1U_0402_25V6  [C_0402]  160.29 87.51 90 bottom
PC1405  1U_0402_6.3V6K  [C_0402]  152.48 86.65 270 bottom
PC1406  2.2U_0402_6.3V6M  [C_0402]  151.59 86.65 270 bottom
PC1407  0.1U_0402_10V7K  [C_0402]  153.05 94.27 270 bottom
PC1408  680P_0603_50V7K  [C_0603]  147.97 93.75 180 bottom
PC1409  330P_0402_50V7K  [C_0402]  155.14 85.75 0 bottom
PC1411  22U_0603_6.3V6M  [C_0603]  142.7 88.03 180 bottom
PC1412  22U_0603_6.3V6M  [C_0603]  142.7 89.24 180 bottom
PC1413  22U_0603_6.3V6M  [C_0603]  142.7 90.45 180 bottom
PC1414  22U_0603_6.3V6M  [C_0603]  142.7 91.65 180 bottom
PC1420  1000P_0402_25V8J  [C_0402]  158.25 94.64 0 bottom
PC1421  1000P_0402_25V8J  [C_0402]  158.25 95.53 0 bottom
PD2  -  [TVNST52302AB0_SOT523-3]  215.21 12.34 180 top
PD3  -  [TVNST52302AB0_SOT523-3]  217.37 12.35 180 top
PD4  -  [TVNST52302AB0_SOT523-3]  157.66 121.75 270 bottom
PD5  -  [BAV99W_SC70-3]  165.88 128.84 180 bottom
PD6  -  [BAV99W_SC70-3]  162.23 126.52 270 bottom
PD102  -  [SDMK0340L-7-F_SOD323-2]  179.6 29.04 0 top
PD704  -  [LRB715FT1G_SOT323-3]  202.14 39.65 0 bottom
PH601  470K_0402_5%_ TSM0B474J4702RE  [R_0402]  157.97 84.02 180 bottom
PH602  10K_0402_5%_ERTJ0ER103J  [R_0402]  154.59 83.97 0 bottom
PH603  470K_0402_5%_ TSM0B474J4702RE  [R_0402]  155.25 74.31 0 bottom
PH604  10KB_0402_5%_ERTJ0ER103J  [R_0402]  142.64 49.3 180 bottom
PH605  10KB_0402_5%_ERTJ0ER103J  [R_0402]  150.72 66.95 180 bottom
PH1101  470K_0402_5%_TSM0B474J4702RE  [R_0402]  46.39 119.64 270 top
PH1102  10K_0402_5%_ERTJ0ER103J  [R_0402]  75.69 110.05 180 bottom
PJP1  JUMP_43X79  [JUMP_43X79-NPM]  159.2 119.84 90 top
PJP2  JUMP_43X79  [JUMP_43X79-NPM]  166.49 120.9 0 top
PJP3  JUMP_43X79  [JUMP_43X79-NPM]  202.94 18.88 90 bottom
PJP102  -  [JUMP_43X118]  160.78 41.11 180 top
PJP103  -  [JUMP_43X118]  173.01 24.01 270 top
PJP105  -  [JUMP_43X79]  175.85 49.34 270 bottom
PJP106  -  [JUMP_43X79]  180.45 39.39 270 bottom
PJP200  -  [JUMP_43X118]  66 102.83 270 top
PJP203  -  [JUMP_43X79]  94.32 102.66 90 bottom
PJP206  -  [JUMP_43X79]  71.3 108.9 180 top
PJP301  -  [JUMP_43X79]  157.34 45.72 180 bottom
PJP302  -  [JUMP_43X118]  138.74 42.82 180 bottom
PJP501  -  [JUMP_43X79]  156.93 38.86 270 bottom
PJP502  -  [JUMP_43X79]  162.97 27.49 270 bottom
PJP601  PAD-OPEN 4X4M  [JUMP_43X118]  166.12 75.08 0 bottom
PJP603  PAD-OPEN1X1M  [JUMP_43X39]  149.42 62.51 0 bottom
PJP701  -  [JUMP_43X118]  200.64 24.9 90 bottom
PJP801  -  [JUMP_43X79]  57.81 5.22 180 bottom
PJP802  -  [JUMP_43X79]  41.81 6.78 90 bottom
PJP1101  -  [JUMP_43X79]  65.41 131.02 270 bottom
PJP1401  -  [JUMP_43X79]  157.92 100.35 270 bottom
PJP1402  -  [JUMP_43X118]  143.47 93.64 90 bottom
PJPDC1  ACES_50458-00601-001  [ACES_50458-00601-001_6P-T]  169.13 124.38 180 top
PL1  HCB3225KF-151T50_2P  [5A_Z150_1210_2P]  159.19 121.71 270 top
PL2  BLM15AG102SN1D_2P  [MURAT_BLM15AG102SN1D_2P]  162.24 122.38 0 top
PL3  HCB3225KF-151T50_2P  [5A_Z150_1210_2P]  202.91 20.78 270 bottom
PL4  HCB3225KF-151T50_2P  [5A_Z150_1210_2P]  168.38 120.93 180 top
PL100  1.5UH_9A_20%_7X7X3_M  [L_7X7X3_M_2P]  171.09 42.63 180 bottom
PL101  2.2UH_7.8A_20%_7X7X3_M  [L_7X7X3_M_2P]  171.85 34.29 270 bottom
PL102  HCB3225KF-151T50_2P  [5A_Z150_1210_2P-NPM]  175.81 50.14 270 bottom
PL103  HCB3225KF-151T50_2P  [5A_Z150_1210_2P-NPM]  180.48 40.2 270 bottom
PL200  1UH_11A_20%_7X7X3_M  [L_7X7X3_M_2P]  69.89 105.11 0 bottom
PL201  HCB3225KF-151T50_2P  [5A_Z150_1210_2P-NPM]  69.45 108.92 0 top
PL301  1UH_6.6A_20%_5X5X3_M  [L_5X5X3_M_2P]  146.25 42.99 180 bottom
PL302  HCB3225KF-151T50_2P  [5A_Z150_1210_2P-NPM]  158.17 45.7 180 bottom
PL501  1UH_6.6A_20%_5X5X3_M  [L_5X5X3_M_2P]  165.12 34.77 270 bottom
PL601  0.68UH +-20% 7.9A  [L_5X5X3_M]  139.72 52.73 0 bottom
PL602  HCB3225KF-151T50_2P  [5A_Z150_1210_2P-NPM]  165.35 75.04 0 bottom
PL603  .15UH +-20% 29A 7X7X4 MOLDING  [L_7X7X4_M]  147.36 71.21 0 bottom
PL605  .15UH +-20% 29A 7X7X4 MOLDING  [L_7X7X4_M]  147.4 80.61 0 bottom
PL700  4.7UH_5.5A_20%_7X7X3_M  [L_7X7X3_M_2P]  209.12 32.15 0 bottom
PL704  1UH_PCMB053T-1R0MS_7A_20%  [L_5X5X3_M_2P-NPM]  200.67 23.28 90 bottom
PL1101  HCB3225KF-151T50_2P  [5A_Z150_1210_2P-NPM]  65.44 129.12 90 bottom
PL1102  0.22UH_24A_20%_7X7X4_MOLDING  [L_7X7X4_M]  82.36 127.46 180 bottom
PL1103  0.22UH_24A_20%_7X7X4_MOLDING  [L_7X7X4_M]  82.31 114.26 180 bottom
PL1401  1UH_6.6A_20%_5X5X3_M  [L_5X5X3_M_2P]  151.71 90.18 180 bottom
PL1402  HCB3225KF-151T50_2P  [5A_Z150_1210_2P-NPM]  157.94 101.17 270 bottom
PQ1  L2N7002DW1T1G_SC88-6  [2N7002DW-T-R7_SOT363-6]  185.11 21.32 0 top
PQ2  L2N7002DW1T1G_SC88-6  [2N7002DW-T-R7_SOT363-6]  179.62 23.57 270 top
PQ3  -  [L2N7002WT1G_SC70-3]  183.18 25.6 90 top
PQ5  MMST3904-7-F_SOT323  [RHU002N06_SOT323-3]  160.99 127.11 180 bottom
PQ6  FDV301N_G 1N SOT23-3  [FDV301N_NL_SOT23-3]  162.58 121.79 180 bottom
PQ201  -  [AON7934_DFN3X3A8-10]  78.93 106.31 0 bottom
PQ601  AON7934_DFN3X3A-8-10  [AON7934_DFN3X3A8-10]  145.86 56.83 45 bottom
PQ704  AON7408L_DFN8-5  [SIS412DN-T1-GE3_POWERPAK8-5]  206.45 31.28 270 bottom
PQ708  AON7506_DFN33-8-5  [SIS412DN-T1-GE3_POWERPAK8-5]  203.56 33.26 90 bottom
PQ709  -  [L2N7002WT1G_SC70-3]  158.1 106.55 90 bottom
PQ710  -  [LMUN5113T1G_SOT323-3]  201.19 23.58 180 top
PQ711  -  [LTC015EUBFS8TL_UMT3F]  199.32 21.68 270 top
PQ712  -  [L2N7002WT1G_SC70-3]  157.78 104.03 270 bottom
PQ717  -  [MDU1512RH_POWERDFN56-8-5]  209.97 27.2 270 bottom
PQ718  -  [MDU1512RH_POWERDFN56-8-5]  162.24 118.72 0 bottom
PQ720  -  [RUM002N02GT2L_VMT3]  187.53 39.9 90 top
PQ721  -  [RUM002N02GT2L_VMT3]  188.04 35.51 180 top
PQ740  -  [MDU1512RH_POWERDFN56-8-5]  160.26 117 270 bottom
PQ1101  AON6552_DFN5X6-8-5  [SIR472DP-T1-GE3_POWERPAK8-5]  73.53 131.79 270 bottom
PQ1102  AON6554_DFN5X6-8-5  [SIR472DP-T1-GE3_POWERPAK8-5]  68.11 122.33 90 bottom
PQ1103  AON6554_DFN5X6-8-5  [SIR472DP-T1-GE3_POWERPAK8-5]  68.11 126.14 270 top
PQ1104  AON6552_DFN5X6-8-5  [SIR472DP-T1-GE3_POWERPAK8-5]  73.51 114.57 270 bottom
PQ1105  AON6554_DFN5X6-8-5  [SIR472DP-T1-GE3_POWERPAK8-5]  68.11 120.35 270 top
PQ1106  AON6554_DFN5X6-8-5  [SIR472DP-T1-GE3_POWERPAK8-5]  68.11 116.54 90 bottom
PR2  1M_0402_1%  [R_0402]  184.88 19.83 180 top
PR3  2.2K_0402_5%  [R_0402]  165.99 125.12 0 bottom
PR4  33_0402_5%  [R_0402]  165.04 124.17 0 bottom
PR5  3.3K_1206_5%  [R_1206]  184.5 25.37 0 top
PR6  100K_0402_1%  [R_0402]  160.1 122.85 270 bottom
PR7  1M_0402_1%  [R_0402]  183.81 22.82 90 top
PR8  10K_0402_1%  [R_0402]  165.06 126.02 270 bottom
PR9  15K_0402_1%  [R_0402]  162.77 129.13 270 bottom
PR10  1M_0402_1%  [R_0402]  183.98 20.83 90 top
PR11  100K_0402_1%  [R_0402]  160.98 125.63 0 bottom
PR12  0_0402_5%  [R_0402]  186.66 19.83 180 top
PR13  0_0402_5%  [R_0402]  188.3 25.88 270 top
PR15  200_0402_5%  [R_0402]  216.91 15.69 270 top
PR16  10K_0402_1%  [R_0402]  217.85 14.76 90 top
PR18  100_0402_5%  [R_0402]  214.75 15.69 270 top
PR20  100_0402_5%  [R_0402]  215.71 15.69 270 top
PR28  10K_0402_1%  [R_0402]  177.38 21.09 90 top
PR29  100K_0402_1%  [R_0402]  178.03 23.71 90 top
PR31  1M_0402_1%  [R_0402]  182.86 22.82 90 top
PR32  100K_0402_1%  [R_0402]  178.05 26.55 270 top
PR33  1M_0402_1%  [R_0402]  182.88 20.68 90 top
PR100  0_0603_5%  [R0603_0OHM]  173.31 45.61 90 bottom
PR102  499K_0402_1%  [R_0402]  179.2 41.36 0 bottom
PR103  499K_0402_1%  [R_0402]  179.2 42.25 0 bottom
PR106  4.7_1206_5%  [R_1206]  169.25 44.6 180 top
PR107  10K_0402_1%  [R_0402]  173.49 37.81 0 bottom
PR108  1K_0402_5%  [R_0402]  174.4 38.7 180 bottom
PR109  150K_0402_1%  [R_0402]  173.49 39.58 0 bottom
PR110  150K_0402_1%  [R_0402]  176.17 39.6 270 bottom
PR111  0_0603_5%  [R0603_0OHM]  177.25 35.77 180 bottom
PR112  4.7_1206_5%  [R_1206]  172.68 34.95 270 top
PR113  10K_0402_1%  [R_0402]  182.19 27.26 0 bottom
PR114  2.2K_0402_5%  [R_0402]  182.66 28.47 180 bottom
PR115  150K_0402_1%  [R_0402]  177.3 29.36 0 bottom
PR116  0_0402_5%  [R0402_0OHM]  178.07 28.46 90 top
PR117  1K_0402_5%  [R_0402]  178.21 28.47 180 bottom
PR118  150K_0402_1%  [R_0402]  179.98 29.37 270 bottom
PR120  0_0402_5%  [R0402_0OHM]  180.87 29.37 270 bottom
PR121  0_0402_5%  [R0402_0OHM]  177.06 39.6 270 bottom
PR122  1M_0402_5%  [R_0402]  181.68 30.69 0 bottom
PR200  0_0603_5%  [R0603_0OHM]  86.51 108.55 0 bottom
PR201  0_0402_5%  [R0402_0OHM]  87.52 100.72 90 bottom
PR202  0_0402_5%  [R0402_0OHM]  90.19 100.72 90 bottom
PR203  4.7_1206_5%  [R_1206]  74.82 102.26 0 top
PR204  100K_0402_1%  [R_0402]  91.08 100.87 270 bottom
PR205  11K_0402_1%  [R_0402]  83.64 105.94 0 bottom
PR206  5.1_0603_5%  [R_0603]  83.14 102.39 0 bottom
PR207  60.4K_0402_1%  [R_0402]  91.95 101.72 90 bottom
PR208  453K_0402_1%  [R_0402]  86.63 100.72 90 bottom
PR209  10K_0402_1%  [R_0402]  85.74 100.72 90 bottom
PR210  2.2_0603_5%  [R_0603]  84.22 103.66 180 bottom
PR301  0_0402_5%  [R0402_0OHM]  154.39 38.62 90 bottom
PR302  1M_0402_1%  [R_0402]  153.5 40.4 90 bottom
PR303  0_0402_5%  [R0402_0OHM]  148.16 38.62 90 bottom
PR304  0_0402_5%  [R0402_0OHM]  153.5 38.62 90 bottom
PR305  0_0402_5%  [R_0402]  152.61 39.53 270 bottom
PR306  0_0603_5%  [R0603_0OHM]  148.8 45.74 90 bottom
PR307  4.7_1206_5%  [R_1206]  146.31 47.07 180 bottom
PR308  10_0402_5%  [R_0402]  149.05 39.53 270 bottom
PR309  21.5K_0402_1%  [R_0402]  150.84 39.52 180 bottom
PR310  31.6K_0402_1%  [R_0402]  151.72 39.53 270 bottom
PR501  0_0402_5%  [R0402_0OHM]  161.7 31.01 180 bottom
PR502  1M_0402_5%  [R_0402]  161.7 31.9 180 bottom
PR503  10_0402_5%  [R_0402]  159.01 31.9 0 bottom
PR504  20K_0402_1%  [R_0402]  158.13 32.8 270 bottom
PR505  10K_0402_1%  [R_0402]  157.38 34.3 135 bottom
PR506  4.7_1206_5%  [R_1206]  166.01 35.07 180 top
PR601  45.3_0402_1%  [R_0402]  165.37 48.87 270 bottom
PR602  0_0402_5%  [R0402_0OHM]  162.59 50.25 180 bottom
PR603  0_0402_5%  [R0402_0OHM]  162.28 48.79 180 top
PR604  75_0402_1%  [R_0402]  164.48 48.87 270 bottom
PR605  100_0402_1%  [R_0402]  163.59 48.87 270 bottom
PR606  0_0402_5%  [R0402_0OHM]  166.52 47.07 90 bottom
PR607  0_0402_5%  [R0402_0OHM]  161.82 48.87 270 bottom
PR608  78.7K_0402_1%  [R_0402]  160.31 48.35 180 top
PR609  0_0402_5%  [R0402_0OHM]  162.71 48.87 270 bottom
PR610  10K_0402_1%  [R_0402]  168.93 51.43 90 top
PR611  48.7K_0402_1%  [R_0402]  160.31 49.24 180 top
PR612  1.91K_0402_1%  [R_0402]  167.15 48.87 270 top
PR613  90.9K_0402_1%  [R_0402]  166.69 50.49 0 bottom
PR616  0_0402_5%  [R0402_0OHM]  168.04 47.95 90 top
PR617  3.6K_0402_1%  [R_0402]  167.22 54.07 270 bottom
PR618  49.9_0402_1%  [R_0402]  165.25 47.95 90 top
PR619  0_0603_5%  [R_0603]  152.29 54.19 180 bottom
PR620  0_0402_5%  [R0402_0OHM]  169.81 49.65 180 top
PR621  1K_0402_1%  [R_0402]  170.72 53.24 180 top
PR622  1.96K_0402_1%  [R_0402]  168.93 54.12 270 top
PR623  2K_0402_1%  [R_0402]  170.72 52.33 180 top
PR624  3.65K_0603_1%  [R_0603]  155.02 49.62 90 top
PR625  0_0402_5%  [R0402_0OHM]  164.36 47.95 90 top
PR626  10_0402_1%  [R_0402]  163.47 47.95 90 top
PR627  4.7_1206_5%  [R_1206]  145.31 52.67 90 top
PR628  4.42K_0402_1%  [R_0402]  171.6 54.43 90 bottom
PR629  84.5K_0402_1%  [R_0402]  166.13 55.27 90 bottom
PR630  4.02K_0402_1%  [R_0402]  161.44 52.04 270 bottom
PR631  27.4K_0402_1%  [R_0402]  169.83 50.55 180 top
PR632  1K_0402_1%  [R_0402]  170.71 56.23 270 top
PR633  11K_0402_1%  [R_0402]  170.71 54.43 90 bottom
PR635  10K_0402_1%  [R_0402]  165.5 58.39 270 top
PR636  1.24K_0402_1%  [R_0402]  159.67 51.01 180 top
PR637  20M_0402_5%  [R_0402]  167.93 55.2 180 bottom
PR638  274_0402_1%  [R_0402]  169.83 56.22 180 top
PR639  3K_0402_1%  [R_0402]  163.46 55.27 90 bottom
PR640  255_0402_1%  [R_0402]  158.84 56.73 180 top
PR641  1K_0402_1%  [R_0402]  157.88 50.11 90 top
PR642  2.61K_0402_1%  [R_0402]  156.1 51.03 270 top
PR643  11K_0402_1%  [R_0402]  158.77 51.89 90 top
PR644  1K_0402_1%  [R_0402]  158.84 57.62 180 top
PR645  316_0402_1%  [R_0402]  164.23 59.22 270 top
PR646  316_0402_1%  [R_0402]  159.73 54.94 180 top
PR647  27.4K_0402_1%  [R_0402]  166.4 59.27 180 top
PR648  1.37K_0402_1%  [R_0402]  163.33 57.43 0 top
PR649  1.69K_0402_1%  [R_0402]  159.73 54.06 180 top
PR650  2K_0402_1%  [R_0402]  165.49 60.16 0 top
PR651  147K_0402_1%  [R_0402]  161.42 54.7 0 bottom
PR652  2K_0402_1%  [R_0402]  159.73 55.82 180 top
PR653  20M_0402_5%  [R_0402]  160.99 57.1 90 bottom
PR654  20M_0402_5%  [R_0402]  156.99 52.81 270 top
PR655  0_0402_5%  [R0402_0OHM]  161.19 84.16 180 bottom
PR656  11K_0402_1%  [R_0402]  159.23 55.84 180 bottom
PR657  4.42K_0402_1%  [R_0402]  160.1 57.1 90 bottom
PR659  0_0402_5%  [R0402_0OHM]  162.31 73.43 0 bottom
PR660  0_0603_5%  [R_0603]  163.65 70.89 180 bottom
PR661  3.65K_0603_1%  [R_0603]  157.18 58.7 0 bottom
PR662  5.11K_0402_1%  [R_0402]  160.6 74.32 0 bottom
PR663  4.7_1206_5%  [R_1206]  155.92 71.02 180 top
PR671  0_0402_5%  [R0402_0OHM]  162.25 83.02 0 bottom
PR672  0_0603_5%  [R_0603]  163.73 80.67 180 bottom
PR673  10_0402_1%  [R_0402]  170.2 57.12 270 bottom
PR674  3.65K_0603_1%  [R_0603]  169.12 56.28 90 bottom
PR676  4.7_1206_5%  [R_1206]  153.75 82.07 270 top
PR678  100_0402_1%  [R_0402]  166.13 47.95 90 top
PR679  0_0402_5%  [R0402_0OHM]  149.76 52.28 180 bottom
PR680  5.11K_0402_1%  [R_0402]  166.39 57.48 90 top
PR703  0.01_1206_1%  [R_1206_4P]  161.5 110.83 0 bottom
PR727  10.5K_0402_1%  [R_0402]  190.72 39.33 180 bottom
PR729  392K_0402_1%  [R_0402]  191.69 31.31 180 bottom
PR731  158K_0402_1%  [R_0402]  190.72 33.11 180 bottom
PR732  53.6K_0402_1%  [R_0402]  190.72 32.22 180 bottom
PR737  3M_0402_5%  [R_0402]  160.42 109.26 270 bottom
PR738  1M_0402_1%  [R_0402]  161.12 106.59 270 bottom
PR740  2_0402_5%  [R_0402]  193.63 30.36 90 bottom
PR741  100K_0402_1%  [R_0402]  189.81 34 0 bottom
PR742  2_0402_5%  [R_0402]  195.28 41.03 90 bottom
PR743  10_1206_5%  [R_1206]  198.2 40.54 0 bottom
PR745  100_0402_1%  [R_0402]  196.17 32.17 270 bottom
PR749  200K_0402_1%  [R_0402]  193.5 40.14 90 top
PR750  200K_0402_1%  [R_0402]  192.61 40.14 90 top
PR751  75K_0402_1%  [R_0402]  196.17 40.17 270 bottom
PR752  66.5K_0402_1%  [R_0402]  191.73 41.06 270 top
PR753  182K_0402_1%  [R_0402]  189.5 42.01 270 bottom
PR754  100_0402_1%  [R_0402]  191.28 42.01 270 bottom
PR755  102K_0402_1%  [R_0402]  192.61 41.06 270 bottom
PR756  10K_0402_1%  [R_0402]  193.52 42.82 180 bottom
PR757  100K_0402_1%  [R_0402]  197.06 40.17 270 bottom
PR760  4.7_0402_5%  [R_0402]  198.39 37.88 270 bottom
PR761  0_0603_5%  [R0603_0OHM]  198.08 34.25 0 bottom
PR762  4.02K_0402_1%  [R_0402]  160.37 121 270 bottom
PR763  4.02K_0402_1%  [R_0402]  161.37 109.26 270 bottom
PR764  10K_0402_1%  [R_0402]  193.5 41.06 270 bottom
PR765  0.01_1206_1%  [R_1206_4P]  213.7 27.9 270 bottom
PR766  4.7_1206_5%  [R_1206]  208.81 30.95 90 top
PR769  0_0402_5%  [R0402_0OHM]  189.81 34.89 0 bottom
PR770  0_0402_5%  [R0402_0OHM]  189.81 35.77 0 bottom
PR771  0_0603_5%  [R0603_0OHM]  198.08 32.98 0 bottom
PR772  0_0402_5%  [R0402_0OHM]  192.74 30.36 90 bottom
PR773  0_0603_5%  [R0603_0OHM]  208.62 23.71 0 top
PR774  1K_0402_1%  [R_0402]  189.81 37.55 0 bottom
PR775  0_0402_5%  [R0402_0OHM]  189.81 38.44 0 bottom
PR776  0_0402_5%  [R0402_0OHM]  194.39 41.03 90 bottom
PR777  0_0402_5%  [R_0402]  189.81 36.66 0 bottom
PR778  0_0402_5%  [R0402_0OHM]  159.48 110.2 180 bottom
PR779  0_0402_5%  [R0402_0OHM]  196.16 41.04 0 bottom
PR780  0_0603_5%  [R_0603]  203.03 22.95 270 top
PR781  10K_0402_5%  [R_0402]  190.66 40.86 180 top
PR790  160K_0402_1%  [R_0402]  187.03 39.03 270 top
PR791  10K_0402_5%  [R_0402]  187.03 41.69 270 top
PR801  21.5K_0402_1%  [R_0402]  45.3 6.71 90 bottom
PR802  10K_0402_1%  [R_0402]  44.32 8.72 0 bottom
PR803  0_0402_5%  [R0402_0OHM]  54.94 7.52 180 bottom
PR1101  100K_0402_1%  [R_0402]  50.22 128.51 270 top
PR1103  0_0603_5%  [R0603_0OHM]  58.25 125.56 0 top
PR1104  10K_0402_1%  [R_0402]  49.12 117.82 180 top
PR1105  10K_0402_1%  [R_0402]  54.06 128.43 270 top
PR1106  10K_0402_1%  [R_0402]  54.95 128.43 270 top
PR1107  4.7_1206_5%  [R_1206]  71.73 128.16 180 top
PR1108  3.65K_0603_1%  [R_0603]  49.17 115.85 180 top
PR1110  1_0402_1%  [R_0402]  49.12 116.93 180 top
PR1111  100K_0402_1%  [R_0402]  49.31 128.52 270 top
PR1112  100K_0402_1%  [R_0402]  48.2 126.76 0 top
PR1113  0_0402_5%  [R_0402]  48.2 125.82 0 top
PR1114  1_0603_5%  [R_0603]  57.23 128.93 270 top
PR1115  0_0402_5%  [R_0402]  48.2 124.04 0 top
PR1116  0_0402_5%  [R0402_0OHM]  48.2 123.15 0 top
PR1117  133K_0402_1%  [R_0402]  48.2 119.59 0 top
PR1119  100K_0402_1%  [R_0402]  48.2 122.29 0 top
PR1120  150K_0402_1%  [R_0402]  47.31 119.63 270 top
PR1121  13.3K_0402_1%  [R_0402]  48.2 118.71 0 top
PR1122  0_0402_5%  [R0402_0OHM]  49.12 121.35 180 top
PR1123  0_0603_5%  [R0603_0OHM]  58.25 120.61 0 top
PR1124  10K_0402_1%  [R_0402]  51.9 112.22 90 top
PR1125  4.7_1206_5%  [R_1206]  73.64 114.64 180 top
PR1126  3.65K_0603_1%  [R_0603]  49.55 112.8 0 top
PR1128  1_0402_1%  [R_0402]  52.79 114.91 270 top
PR1129  301_0402_1%  [R_0402]  55.71 116.37 270 top
PR1130  121K_0402_1%  [R_0402]  59.38 118.71 0 top
PR1131  2.61K_0402_1%  [R_0402]  50.11 113.88 0 top
PR1132  11K_0402_1%  [R_0402]  50.11 114.77 0 top
PR1133  1K_0402_1%  [R_0402]  53.92 115.47 0 top
PR1134  22.1K_0402_1%  [R_0402]  57.61 117.83 270 top
PR1135  2K_0402_1%  [R_0402]  56.58 115.91 0 top
PR1136  470_0402_1%  [R_0402]  52.15 117.8 90 top
PR1137  100_0402_1%  [R_0402]  53.04 115.9 90 top
PR1138  0_0402_5%  [R0402_0OHM]  53.92 117.75 0 top
PR1139  0_0402_5%  [R0402_0OHM]  56.61 117.75 180 top
PR1140  32.4K_0402_1%  [R_0402]  53.17 127.52 90 top
PR1401  100K_0402_5%  [R_0402]  160.31 89.3 180 bottom
PR1402  0_0603_5%  [R0603_0OHM]  154.13 92.86 90 bottom
PR1403  0_0402_5%  [R0402_0OHM]  160.8 85.74 90 bottom
PR1404  1M_0402_1%  [R_0402]  159.4 87.51 90 bottom
PR1405  0_0402_5%  [R0402_0OHM]  153.37 85.74 90 bottom
PR1406  0_0402_5%  [R_0402]  159.4 85.74 90 bottom
PR1407  0_0402_5%  [R_0402]  157.82 86.65 270 bottom
PR1408  4.7_1206_5%  [R_1206]  151.85 94.13 180 bottom
PR1409  10_0402_5%  [R_0402]  154.26 86.65 270 bottom
PR1410  30.1K_0402_1%  [R_0402]  156.05 86.64 180 bottom
PR1411  24K_0402_1%  [R_0402]  156.93 86.65 270 bottom
PU100  SY8286BRAC_QFN20_3X3  [SY8286BRAC_QFN20_3X3-S]  174.67 44.15 270 bottom
PU102  SY8286CRAC_QFN20_3X3  [SY8286CRAC_QFN20_3X3-S]  177.36 34.15 270 bottom
PU200  RT8207PGQW_WQFN20_3X3  [RT8207PGQW_WQFN20_3X3-S]  89.48 105.72 270 bottom
PU300  SY8286RAC_QFN20_3X3  [SY8286RAC_QFN20_3X3-S]  149.67 44.2 270 bottom
PU500  RT8061AZQW_WDFN10_3X3  [SY8033BDBC_DFN10_3X3-S]  161.39 35.95 270 bottom
PU602  ISL95859HRTZ-T_TQFN40_5X5  [ISL62883CHRTZ-T_TQFN40_5X5-S]  166.96 51.32 90 top
PU603  -  [AOZ5019QI_QFN23_5X3P5]  160.97 72.4 270 bottom
PU605  -  [AOZ5019QI_QFN23_5X3P5]  161.02 82.06 270 bottom
PU606  ISL95808HRZ-TS2378_DFN8_2X2  [ISL95808HRZ-TS2378_DFN8_2X2-S]  153.33 52.85 270 bottom
PU703  ISL88739HRZ-T_QFN32_4X4  [ISL95520HRZ-T_QFN32_4X4-S]  192.42 34.44 0 bottom
PU800  RT9059GSP_SO8  [RT904225GSP_SO8]  52.25 8.51 270 bottom
PU1100  ISL62771HRTZ-T_TQFN40_5X5  [ISL62771HRTZ-T_TQFN40_5X5-S]  51.2 125.04 270 top
PU1400  SY8286RAC_QFN20_3X3  [SY8286RAC_QFN20_3X3-S]  155.19 91.51 270 bottom
Q1  -  [2N7002K_SOT23-3]  42.08 3.33 270 bottom
Q2  -  [DMN66D0LDW-7_SOT363-6]  155.41 5.94 270 top
Q3  -  [DDTA144VCA-7-F_SOT23-3]  154.43 9.1 270 top
Q4  -  [DDTA144VCA-7-F_SOT23-3]  149.79 10.06 270 top
Q5  -  [2N7002K_SOT23-3]  153.52 6.06 90 top
Q6  -  [LN2306LT1G_SOT23-3]  79.9 3.05 0 top
Q7  -  [DDTA144VCA-7-F_SOT23-3]  83.84 6.02 180 top
Q8  -  [LN2306LT1G_SOT23-3]  113.28 7.07 270 top
Q9  -  [LN2306LT1G_SOT23-3]  102.51 5.21 0 top
Q10  -  [DMN66D0LDW-7_SOT363-6]  106.4 7.9 180 top
Q11  -  [DMN66D0LDW-7_SOT363-6]  134.03 20.41 270 bottom
Q12  NTK3139PT1G_SOT723-3  [2N7002K_SOT23-3]  97.45 5.99 90 top
Q13  -  [2N7002K_SOT23-3]  89.2 6.06 90 top
Q14  -  [LMBT3904LT1G_SOT23-3]  53.46 11.64 90 bottom
Q15  -  [DDTA144VCA-7-F_SOT23-3]  175.91 19.35 180 top
Q16  -  [LN2306LT1G_SOT23-3]  174.3 13.11 90 top
QA1  -  [LN2306LT1G_SOT23-3]  40.48 12.63 0 top
QC1  -  [DMN66D0LDW-7_SOT363-6]  113.86 22.63 0 top
QC2  -  [2N7002K_SOT23-3]  88.41 18.54 180 top
QI1  -  [2N7002K_SOT23-3]  15.36 77.86 270 top
QI2  -  [DMN66D0LDW-7_SOT363-6]  32.96 94.91 135 top
QI3  2N7002W-7-F_1N_SOT323-3  [SSM3K7002FU_SC70-3]  28.08 92.54 90 top
QV1  DMN66D0LDW-7 2N SOT363-6  [2N7002KDWH_SOT363-6]  114.08 103.37 180 top
R1  1K_0402_5%  [R_0402]  30.7 7.96 180 bottom
R2  10M_0402_5%  [R_0402]  37.93 4.14 90 top
R3  0_0805_5%  [R_0805]  222.97 28.05 270 bottom
R5  10K_0402_5%  [R_0402]  220.73 45.93 0 bottom
R6  0_0402_5%  [R_0402]  221.65 45.05 180 bottom
R8  0_0402_5%  [R0402_0OHM]  218.71 22.36 90 bottom
R9  0_0402_5%  [R_0402]  218.71 22.36 90 top
R10  100K_0402_5%  [R_0402]  224.49 22.36 0 bottom
R11  0_0603_5%  [R_0603]  228.56 34.95 0 top
R12  0_0603_5%  [R_0603]  227.48 29.93 180 top
R13  0_0603_5%  [R_0603]  225.06 29.93 180 top
R16  0_0603_5%  [R_0603]  227.54 34.95 180 top
R17  0_0402_5%  [R_0402-NPM]  221.58 35.33 180 bottom
R18  0_0402_5%  [R_0402-NPM]  221.58 34.44 180 bottom
R19  33_0402_5%  [R_0402]  221.06 30.9 270 top
R20  0_0402_5%  [R_0402]  220.68 26.64 270 bottom
R21  0_0402_5%  [R_0402]  221.57 26.64 270 bottom
R22  100_0402_5%  [R_0402]  156.1 105.89 90 top
R23  10K_0402_5%  [R_0402]  149.5 5.85 90 top
R24  100K_0402_5%  [R_0402]  80.68 6.82 180 top
R25  1K_0402_5%  [R_0402]  85.3 6.81 90 top
R26  51K_0402_5%  [R_0402]  119.46 11.59 270 bottom
R27  100K_0402_5%  [R_0402]  120.34 11.51 0 bottom
R28  18.7K_0402_1%  [R_0402]  138.45 16.93 270 bottom
R29  2K_0402_1%  [R_0402]  130.24 19.82 270 bottom
R30  10K_0402_5%  [R_0402]  183.48 52.35 225 top
R31  4.7K_0402_5%  [R_0402]  110.71 7.44 270 top
R32  4.7K_0402_5%  [R_0402]  111.6 7.44 270 top
R33  4.7K_0402_5%  [R_0402]  105.89 4.98 180 top
R34  4.7K_0402_5%  [R_0402]  105.99 8.86 0 top
R35  0_0402_5%  [R_0402]  91.76 5.74 0 top
R36  0_0603_5%  [R_0603]  87.14 3.58 270 top
R37  100_0603_1%  [R_0603]  88.35 3.58 270 top
R38  20K_0402_1%  [R_0402]  93.55 8.36 270 top
R39  10K_0402_5%  [R_0402]  101.89 9.04 180 top
R40  4.7K_0402_5%  [R_0402]  103.66 9.02 180 top
R41  100K_0402_5%  [R_0402]  96.74 8.4 90 top
R42  24.9K_0402_1%  [R_0402]  110.43 9.73 0 bottom
R43  10K_0402_1%  [R_0402]  92.03 8.92 270 bottom
R44  THINK_0603_1%_TSM1B104F3591RZ  [R_0603]  108.03 22.37 180 top
R45  0_0402_5%  [R_0402]  91.21 6.23 90 bottom
R46  2.2K_0402_5%  [R_0402]  107.46 6.83 270 top
R47  2.2K_0402_5%  [R_0402]  104.54 9.87 270 top
R48  2.2K_0402_5%  [R_0402]  134.98 19.68 90 bottom
R49  2.2K_0402_5%  [R_0402]  131.17 19.84 270 bottom
R50  10K_0402_5%  [R_0402]  182.78 52.99 225 top
R51  0_0805_5%  [R0805_0OHM]  223.98 48.45 90 top
R53  100K_0402_5%  [R_0402]  170.52 13.37 270 top
R54  0_0805_5%  [R_0805]  224.01 41.62 180 top
R55  0_0603_5%  [R0603_0OHM]  184.98 54.9 135 top
R56  0_0402_5%  [R_0402]  222.28 37.17 180 bottom
R57  10K_0402_5%  [R_0402]  226.45 27.35 180 bottom
RA1  0_0805_5%  [R0805_0OHM]  37.93 23.68 90 top
RA2  0_0402_5%  [R0402_0OHM]  25.36 25.54 90 top
RA3  100K_0402_5%  [R_0402]  24.32 24.78 90 top
RA4  0_0603_5%  [R0603_0OHM]  34.04 11.53 135 top
RA5  0_0402_5%  [R0402_0OHM]  36.24 16.43 0 top
RA6  0_0402_5%  [R0402_0OHM]  38.87 16.46 0 top
RA7  33_0402_5%  [R_0402]  28.28 26.76 270 top
RA8  100K_0402_5%  [R_0402]  33.88 24.6 180 top
RA9  0_0402_5%  [R_0402]  30.44 25.54 90 top
RA10  200K_0402_1%  [R_0402]  21.53 23.46 0 top
RA11  0_0402_5%  [R_0402]  19.58 24.52 90 top
RA12  0_0402_5%  [R_0402]  20.53 24.52 90 top
RA13  BLM15PD800SN1D_2P  [MURAT_BLM15PD600SN1D_2P]  32.59 4.6 180 top
RA14  BLM15PD800SN1D_2P  [MURAT_BLM15PD600SN1D_2P]  32.65 2.37 180 top
RA15  BLM15PD800SN1D_2P  [MURAT_BLM15PD600SN1D_2P]  32.65 8.34 180 top
RA16  BLM15PD800SN1D_2P  [MURAT_BLM15PD600SN1D_2P]  32.65 6.37 180 top
RA17  0_0402_5%  [R0402_0OHM]  23.2 25.43 270 top
RA18  0_0402_5%  [R0402_0OHM]  32.63 14.39 0 top
RA22  0_0805_5%  [R0805_0OHM]  18.18 25.77 270 top
RA23  1K_0402_5%  [R_0402]  16.78 29.56 270 top
RA24  10K_0402_5%  [R_0402]  17.66 28.66 0 top
RA25  2.2K_0402_5%  [R_0402]  22.75 15.98 270 bottom
RA26  2.2K_0402_5%  [R_0402]  22.63 16.9 90 bottom
RA27  10_0402_1%  [R_0402]  25.81 11.19 180 bottom
RA28  1K_0402_5%  [R_0402]  25.81 10.31 180 bottom
RA29  4.7K_0402_5%  [R_0402]  25.81 12.08 180 bottom
RA30  10K_0402_5%  [R_0402]  22.99 10.31 0 bottom
RA31  10_0402_1%  [R_0402]  23.65 12.15 180 bottom
RA32  1K_0402_5%  [R_0402]  23.65 13.04 180 bottom
RA33  4.7K_0402_5%  [R_0402]  23.65 13.92 180 bottom
RA34  10K_0402_5%  [R_0402]  21.42 13.05 270 bottom
RA35  BLM15PX330SN1D_2P  [MURAT_BLM15PX330SN1D_2P]  21.67 15.01 90 bottom
RA36  0_0402_5%  [R0402_0OHM]  21.47 11.28 270 bottom
RA37  0_0402_5%  [R0402_0OHM]  21.41 14.06 180 bottom
RA38  BLM15PX330SN1D_2P  [MURAT_BLM15PX330SN1D_2P]  21.61 17.79 270 bottom
RA39  0_0603_5%  [R0603_0OHM]  15.64 18.82 90 bottom
RA40  0_0402_5%  [R0402_0OHM]  15.12 21.23 0 bottom
RA41  100K_0402_5%  [R_0402]  25.7 12.99 90 top
RA42  33_0402_5%  [R_0402]  31.71 26.13 270 top
RC1  2.2K_0402_5%  [R_0402]  124.99 25.17 270 bottom
RC2  2.2K_0402_5%  [R_0402]  124.1 25.17 270 bottom
RC3  10K_0402_5%  [R_0402]  128.4 28.92 0 bottom
RC4  24.9_0402_1%  [R_0402]  120.35 58.13 270 top
RC5  10K_0402_5%  [R_0402]  119.39 28.98 0 top
RC6  100K_0402_5%  [R_0402]  114.83 20.34 0 bottom
RC7  100_0402_1%  [R_0402]  128.28 33.55 0 bottom
RC8  200_0402_1%  [R_0402]  105.06 24.51 0 bottom
RC9  100K_0402_5%  [R_0402]  92.34 81.03 270 top
RC10  121_0402_1%  [R_0402]  92.55 38.05 180 top
